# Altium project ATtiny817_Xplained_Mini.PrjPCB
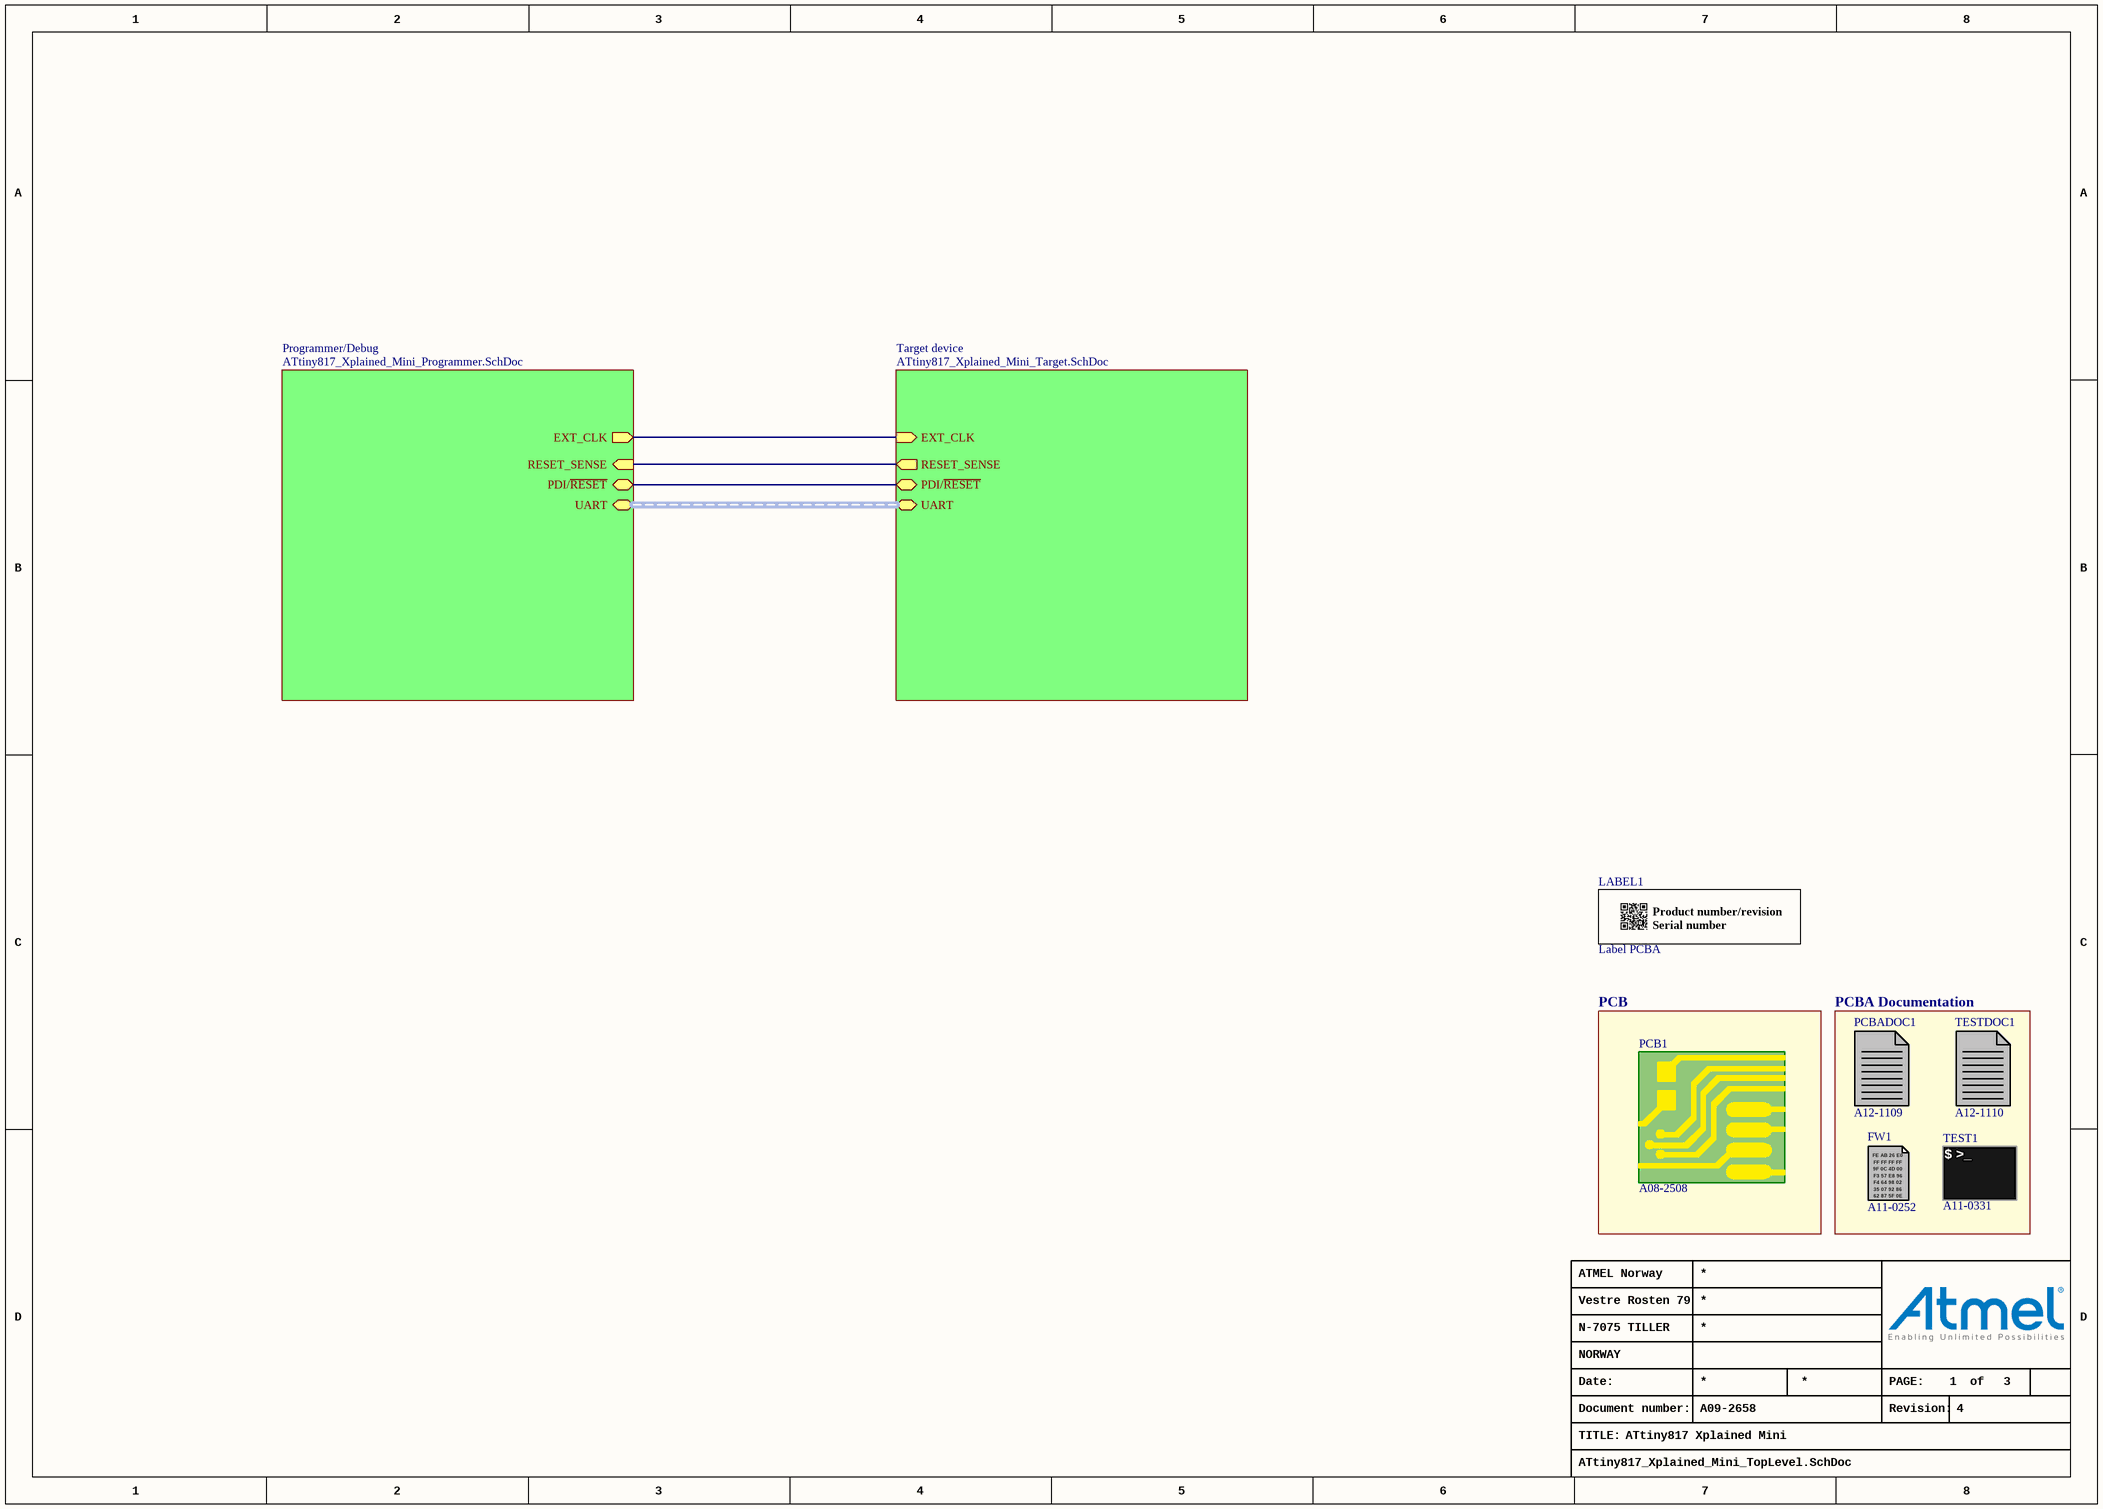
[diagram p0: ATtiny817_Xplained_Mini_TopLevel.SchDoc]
3 sheets, 69 parts. Net scope: hierarchical (ports join the sheet entries above them; power ports are global).
Board file: ATtiny817_Xplained_Mini.PcbDoc
Sheets:
  ATtiny817_Xplained_Mini_TopLevel.SchDoc
    Programmer/Debug = ATtiny817_Xplained_Mini_Programmer.SchDoc
    Target device = ATtiny817_Xplained_Mini_Target.SchDoc

## Sheet ATtiny817_Xplained_Mini_TopLevel.SchDoc: ATtiny817 Xplained Mini
size A3; Organization: ATMEL Norway; Address1: Vestre Rosten 79; Address2: N-7075 TILLER; Address3: NORWAY; DocumentNumber: A09-2658; Revision: 4; SheetNumber: 1; SheetTotal: 3; PageSetup: Record=PageOptions¦CenterHorizontal=True¦CenterVertical=True¦PrintScale=1.01¦XCorrection=1.00¦YCorrection=1.00¦PrintKind=1¦BorderSize=5000000¦LeftOffset=0¦BottomOffset=0¦Orientation=2¦PaperLength=1000¦PaperWidth=1000¦Scale=100¦PaperSource=7¦PrintQuality=-4¦MediaType=1¦DitherType=10¦PaperKind=Letter¦PrintScaleMode=1

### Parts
FW1  AN: A11-0252  (mechanical)
LABEL1  value Label PCBA  [AP8-00317]
PCB1  AN: A08-2508  (mechanical)
PCBADOC1  AN: A12-1109  (mechanical)
TEST1  AN: A11-0331  (mechanical)
TESTDOC1  AN: A12-1110  (mechanical)

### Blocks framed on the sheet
PCB: PCB1
PCBA Documentation: FW1 PCBADOC1 TEST1 TESTDOC1

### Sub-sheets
Programmer/Debug = ATtiny817_Xplained_Mini_Programmer.SchDoc: EXT_CLK (out), UART (harness UART), RESET_SENSE (in), PDI/~{RESET} (bidir)
Target device = ATtiny817_Xplained_Mini_Target.SchDoc: EXT_CLK (in), UART (harness UART), RESET_SENSE (out), PDI/~{RESET} (bidir)

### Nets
CLK_OUT: sheet Programmer/Debug/EXT_CLK, sheet Target device/EXT_CLK
RESET_SENSE: sheet Programmer/Debug/RESET_SENSE, sheet Target device/RESET_SENSE
UPDI: sheet Programmer/Debug/PDI/~{RESET}, sheet Target device/PDI/~{RESET}

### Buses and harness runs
harness sheet Programmer/Debug/UART = sheet Target device/UART

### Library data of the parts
FW1 = A11-0252: MEDBG firmware; PartGroup: Software,Firmware,Tools
LABEL1 = A09-0611: PCBA identification label PP Top White Gloss; PartGroup: Mechanical devices,Packaging materials,Printed Labels; Manufacturer: ACT Logimark AS; MPN: 505462
PCB1 = A08-2508: ATtiny807 Xplained Mini PCB documentation; PartGroup: Mechanical devices,Printed circuit boards; Value: ATtiny817 Xplained Mini PCB documentation
PCBADOC1 = A12-1109: ATtiny807 Xplained Mini PCBA documentation; PartGroup: Documentation,PCBA Documents,Atmel; Value: A09-2658 PCBA Files
TEST1 = A11-0331: Fixture test for ATtiny807 Xplained Pro; PartGroup: Software,Test software,Starter Kit; Value: ATtiny817 Xplained Mini test
TESTDOC1 = A12-1110: ATtiny807 Xplained Mini Test Instructions; PartGroup: Documentation,Procedures,Test Instructions; Value: ATtiny817 Xplained Mini Test Instructions

## Sheet ATtiny817_Xplained_Mini_Programmer.SchDoc: ATtiny817 Xplained Mini
size A3; Organization: ATMEL Norway; Address1: Vestre Rosten 79; Address2: N-7075 TILLER; Address3: NORWAY; DocumentNumber: A09-2658; Revision: 4; SheetNumber: 3; SheetTotal: 3; PageSetup: Record=PageOptions¦CenterHorizontal=True¦CenterVertical=True¦PrintScale=1.01¦XCorrection=1.00¦YCorrection=1.00¦PrintKind=1¦BorderSize=5000000¦LeftOffset=0¦BottomOffset=0¦Orientation=2¦PaperLength=1000¦PaperWidth=1000¦Scale=100¦PaperSource=7¦PrintQuality=-4¦MediaType=1¦DitherType=10¦PaperKind=A3 (297 x 420 mm)¦PrintScaleMode=1
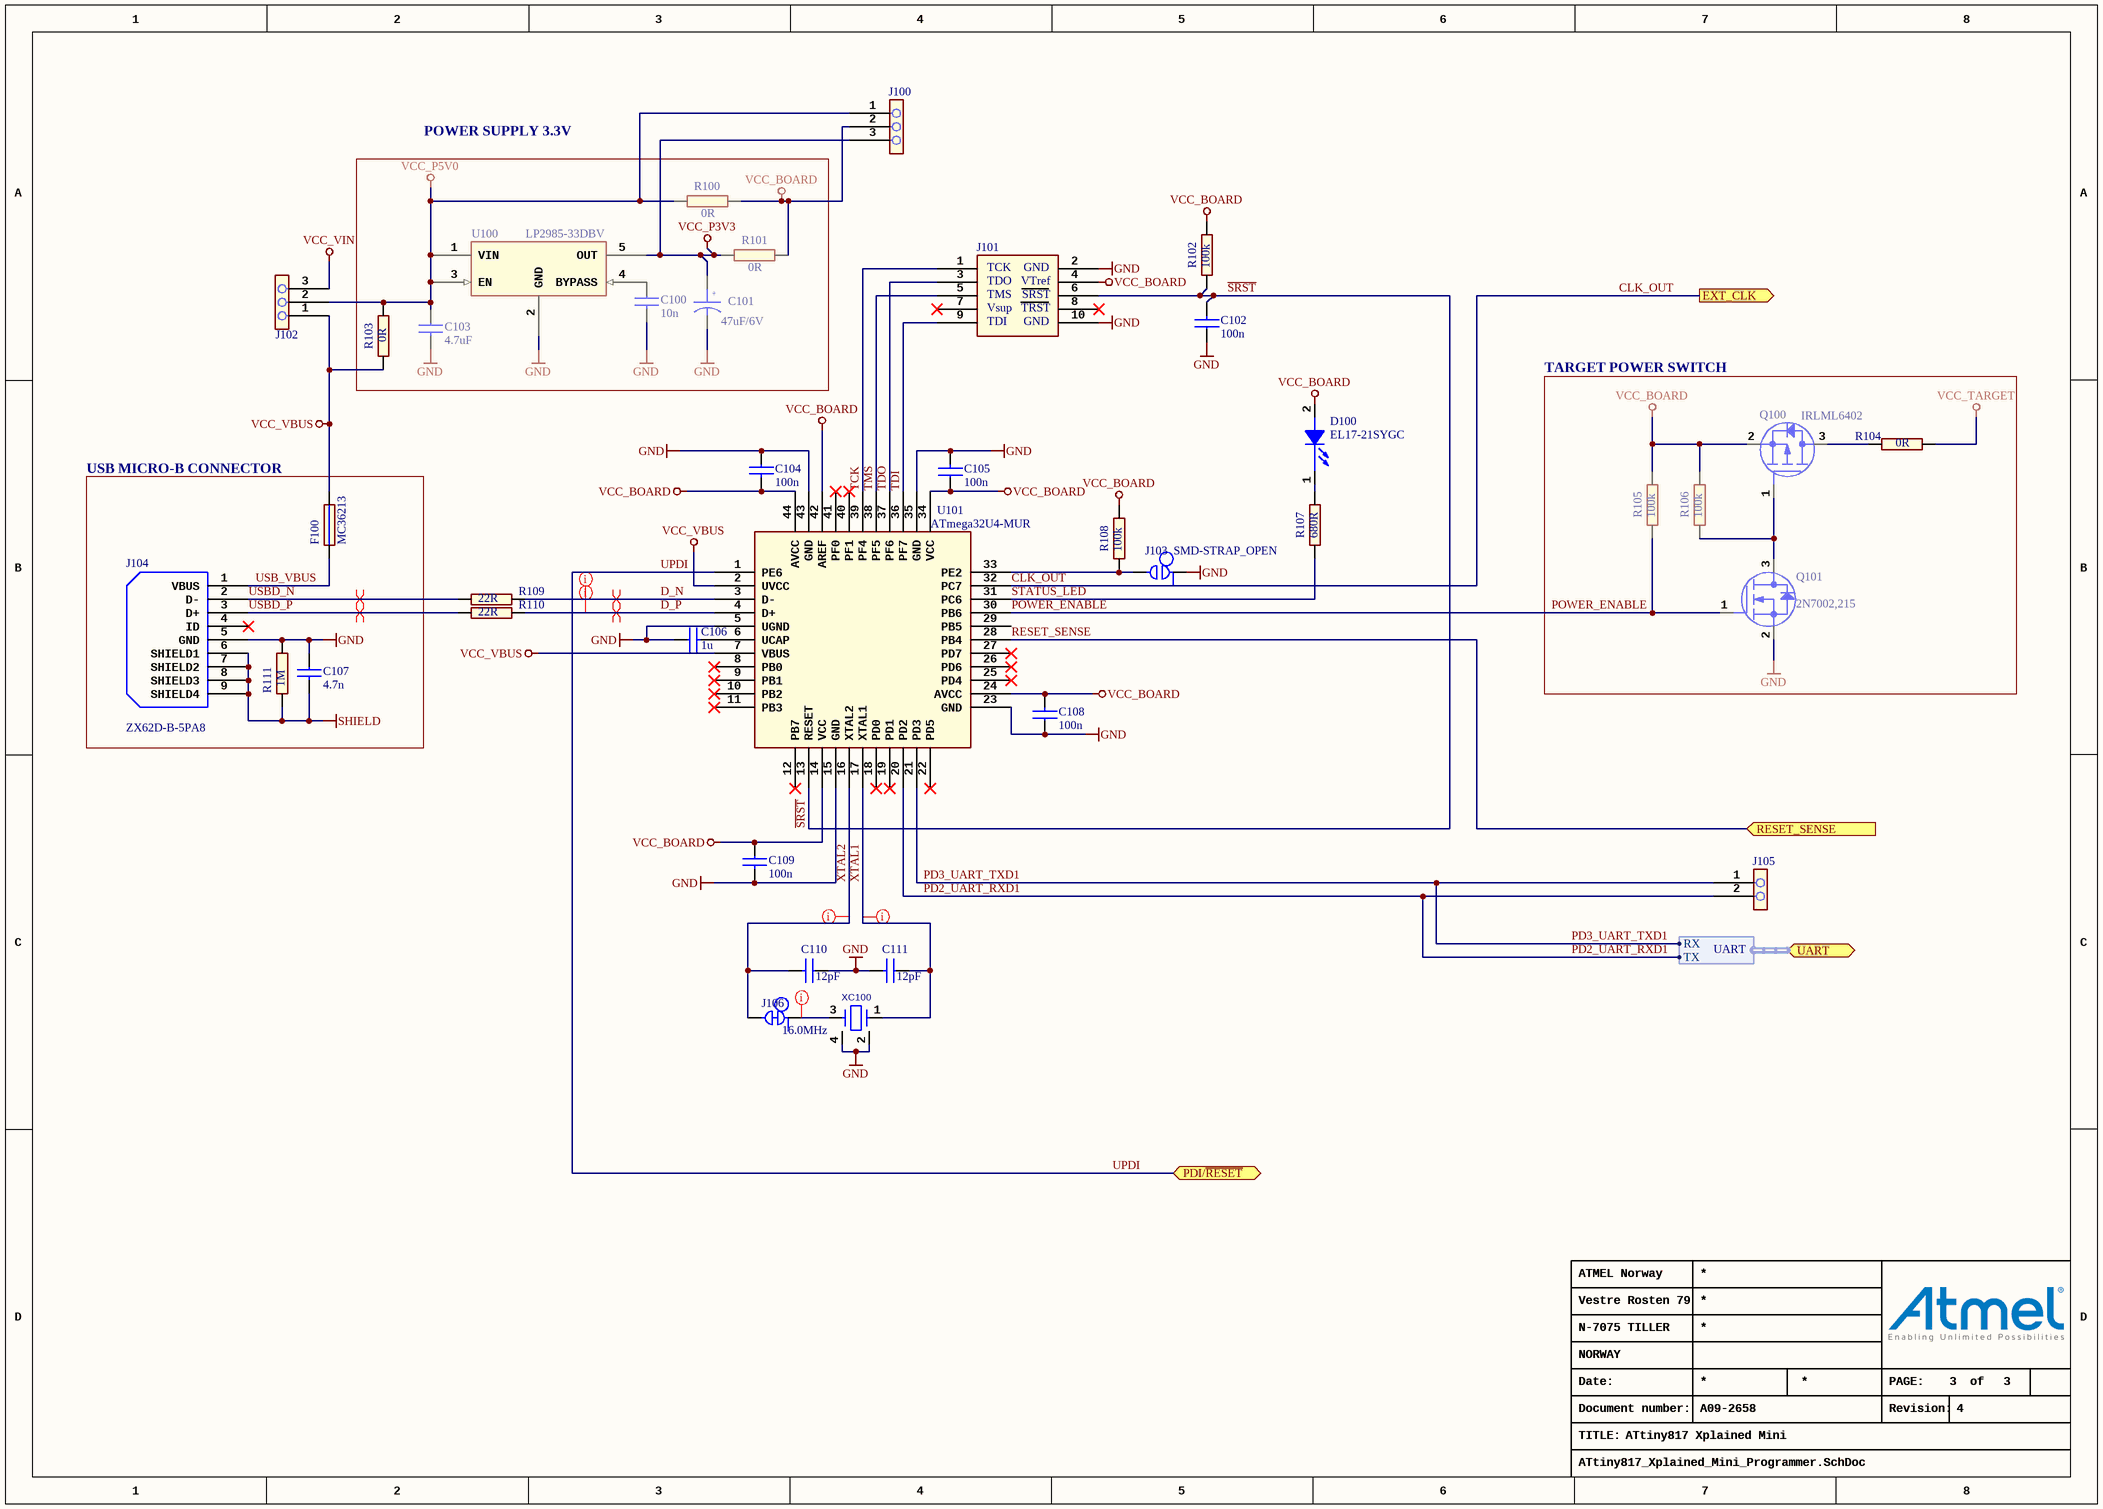
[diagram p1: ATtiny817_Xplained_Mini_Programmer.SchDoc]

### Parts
C100  value 10n  [AP1-00001]
C101  value 47uF/6V  [AP1-00008]
C102  value 100n  [AP1-00001]
C103  value 4.7uF  [AP1-00002]  (hidden comment: Farnell no.: 1833806)
C104  value 100n  [AP1-00001]
C105  value 100n  [AP1-00001]
C106  value 1u  [AP1-00001]
C107  value 4.7n  [AP1-00001]
C108  value 100n  [AP1-00001]
C109  value 100n  [AP1-00001]
C110  value 12pF  [AP1-00038]
C111  value 12pF  [AP1-00038]
D100  value EL17-21SYGC  [AP4-00013]
F100  value MC36213  [AP2-00002]  (hidden comment: Farnell no: 1861197)
J100  (no value)  [AP8-00745]
J101  (no value)  [AP8-00257]
J102  (no value)  [AP8-00745]
J103  value SMD-STRAP_OPEN  [AP9-00034]  (no BOM)
J104  value ZX62D-B-5PA8  [AP8-00851]  (hidden comment: 2,000 pieces per reel)
J105  (no value)  [AP8-00733]
J106  (no value)  [AP9-00044]  (net tie, no BOM)
Q100  value IRLML6402  [AP5-00002]
Q101  value 2N7002,215  [AP5-00002]
R100  value 0R  [AP2-00000]
R101  value 0R  [AP2-00000]
R102  value 100k  [AP2-00000]
R103  value 0R  [AP2-00000]
R104  value 0R  [AP2-00000]
R105  value 100k  [AP2-00000]
R106  value 100k  [AP2-00000]
R107  value 680R  [AP2-00000]
R108  value 100k  [AP2-00000]
R109  value 22R  [AP2-00000]
R110  value 22R  [AP2-00000]
R111  value 1M  [AP2-00000]
U100  value LP2985-33DBV  [AP6-00087]
U101  value ATmega32U4-MUR  [AP6-00375]
XC100  value 16.0MHz  [AP7-00061]

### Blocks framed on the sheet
POWER SUPPLY 3.3V: C100 C101 C103 R100 R101 R103 U100
TARGET POWER SWITCH: Q100 Q101 R104-R106
USB MICRO-B CONNECTOR: C107 F100 J104 R111

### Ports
EXT_CLK (out), PDI/~{RESET}, RESET_SENSE (in), UART (harness UART)

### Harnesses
UART: RX, TX

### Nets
GND: C100.2 C101.2 C102.1 C103.2 C104.1 C105.2 C106.1 C107.1 C108.1 C109.2 C110.1 C111.2 J101.2 J101.10 J103.1 J104.5(GND) Q101.2(S) R111.2 U100.2(GND) U101.5(UGND) U101.15(GND) U101.23(GND) U101.35(GND) U101.43(GND) U101.45(GND) XC100.2(GND) XC100.4(GND)
SHIELD: C107.2 J104.6(SHIELD1) J104.7(SHIELD2) J104.8(SHIELD3) J104.9(SHIELD4) R111.1
VCC_BOARD: C104.2 C105.1 C108.2 C109.1 D100.2(ANODE) J100.2 J101.4 Q100.2(S) R100.1 R101.2 R102.2 R105.2 R106.2 R108.2 U101.14(VCC) U101.24(AVCC) U101.34(VCC) U101.42(AREF) U101.44(AVCC)
VCC_P3V3: C101.1 J100.3 R101.1 U100.5(OUT)
VCC_P5V0: C103.1 J100.1 J102.2 R100.2 R103.2 U100.1(VIN) U100.3(EN)
VCC_TARGET: R104.2
VCC_VBUS: F100.2 J102.1 R103.1 U101.2(UVCC) U101.7(VBUS)
VCC_VIN: J102.3
CLK_OUT: U101.32(PC7) ; port EXT_CLK
D_N: R109.2 U101.3(D-)
D_P: R110.2 U101.4(D+)
PD2_UART_RXD1: J105.2 U101.20(PD2) ; port UART.TX
PD3_UART_TXD1: J105.1 U101.21(PD3) ; port UART.RX
POWER_ENABLE: Q101.1(G) R105.1 U101.30(PB6)
RESET_SENSE: U101.28(PB4) ; port RESET_SENSE
~{SRST}: C102.2 J101.6 R102.1 U101.13(RESET)
STATUS_LED: R107.2 U101.31(PC6)
TCK: J101.1 U101.39(PF4)
TDI: J101.9 U101.36(PF7)
TDO: J101.3 U101.37(PF6)
TMS: J101.5 U101.38(PF5)
UPDI: U101.1(PE6) ; port PDI/~{RESET}
USB_VBUS: F100.1 J104.1(VBUS)
USBD_N: J104.2(D-) R109.1
USBD_P: J104.3(D+) R110.1
XTAL1: C111.1 U101.17(XTAL1) XC100.1(IN)
XTAL2: C110.2 J106.2 U101.16(XTAL2)
NetC100_1: C100.1 U100.4(BYPASS)
NetC106_2: C106.2 U101.6(UCAP)
NetD100_1: D100.1(CATHODE) R107.1
NetJ103_2: J103.2 R108.1 U101.33(PE2)
NetJ106_1: J106.1 XC100.3(OUT)
NetQ100_1: Q100.1(G) Q101.3(D) R106.1
NetQ100_3: Q100.3(D) R104.1

Not connected (* = marked no-connect by the designer): J101 7* 8*; J104 4(ID)*; U101 8(PB0)* 9(PB1)* 10(PB2)* 11(PB3)* 12(PB7)* 18(PD0)* 19(PD1)* 22(PD5)* 25(PD4)* 26(PD6)* 27(PD7)* 29(PB5) 40(PF1)* 41(PF0)*

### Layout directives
differential pair: D_N, D_P, USBD_N, USBD_P
rule Assembly Testpoint Usage [Testpoint - Not Allowed    Multiple - Not Allowed]: D_N, D_P, NetJ106_1, XTAL1, XTAL2

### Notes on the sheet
- Date:
- PAGE:
- of
- TITLE:
- Document number:
- Revision:

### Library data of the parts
C100 = A01-0050: Ceramic capacitor, SMD 0402, X7R, 25V, +/-10%; PartGroup: Capacitors,Ceramic,SMD 0402; Manufacturer: YAGEO CORP; MPN: CC0402KRX7R8BB103; TemperatureRange: -55 - +125 deg C
C101 = A01-0292: SMD tantalum capacitor, precision molded chip, ESR=0,5; PartGroup: Capacitors,Tantalum; Manufacturer: Kemet; MPN: T494B476M006AT; TemperatureRange: -55 to +85 deg.C
C102 C104 C105 C108 C109 = A01-0246: Ceramic capacitor, SMD 0402, X7R, 16V, +/-10%; PartGroup: Capacitors,Ceramic,SMD 0402; Manufacturer: Kemet; MPN: C0402C104K4RACTU; TemperatureRange: -55 - +125 deg C
C103 = A01-0502: Ceramic capacitor, SMD 0603, X5R, 10V, ±10 %; PartGroup: Capacitors,Ceramic,SMD 0603; Manufacturer: AVX; MPN: 0603ZD475KAT2A; Tolerance: Â±10%; TemperatureRange: Ã‚â€“55 to +85 deg C
C106 = A01-0286: Ceramic capacitor, SMD 0402, X5R, 6.3V, +/-10% (de26942); PartGroup: Capacitors,Ceramic,SMD 0402; Manufacturer: Kemet; MPN: C0402C105K9PAC; TemperatureRange: -55 to 85 deg C
C107 = A01-0046: Ceramic capacitor, SMD 0402, X7R, 25V, +/-10% (de35287); PartGroup: Capacitors,Ceramic,SMD 0402; Manufacturer: PHYCOMP; MPN: 2238 587 15632; TemperatureRange: -55 - +125 deg C
C110 C111 = A01-0355: Ceramic capacitor, SMD 0402, NP0, 50V, +/-5% (de19819); PartGroup: Capacitors,Ceramic,SMD 0402; Manufacturer: Kyocera-elco; MPN: CM05CG120J50AH; Tolerance: 5%; TemperatureRange: -55 - +125 deg C
D100 = A10-0018: LED, Green, Wave length=575nm, SMD 0805, ±70°; PartGroup: Opto,LEDs,SMD; Manufacturer: Everlight; TemperatureRange: -40 - +85 deg C
F100 = A02-0622: Resetable PTC fuse, Ih = 0.5A, It = 1.0A, 0805 package; PartGroup: Resistors,Resettable fuses,SMD; Manufacturer: Multicomp; TemperatureRange: -40°C to + 85°C
J100 J102 = A08-1799: 1x3 pin header, 2.54mm pitch, Pin-in-Paste THM, 1mm hole; PartGroup: Mechanical devices,Connectors,Pin headers; Manufacturer: SAMTEC; Value: HMTSW-103-23-F-S-237
J101 = A08-0385: 2x5 pin header, 1.27mm pitch, THM; PartGroup: Mechanical devices,Connectors,Pin headers; Manufacturer: Garry; MPN: 176-2-010-0-T-XS0-0730; Value: PIN HEADER 2x5
J103 = A09-0483: Default open SMD strap; PartGroup: Mechanical devices,PCB implemented components
J104 = A08-2092: Micro USB B Connector, Standard SMT + DIP; PartGroup: Mechanical devices,Connectors,USB; Manufacturer: HIROSE; MPN: ZX62D-B-5PA8(30)
J105 = A08-1754: 1x2 pin header, 2.54mm pitch, Pin-in-Paste THM; PartGroup: Mechanical devices,Connectors,Pin headers; Manufacturer: SAMTEC; Value: HMTSW-102-23-F-S-237; TemperatureRange: - 55 deg C to + 125 deg C
J106 = A09-0783: Default closed SMD strap, 0603 size; PartGroup: Mechanical devices,PCB implemented components; Value: SMD-STRAP_0603_CLOSED
Q100 = A05-0087: P-ch. MOSFET. -30V, -3.7A continuous,RDS(ON)=0.05Ohm@VGS=-4,5V, RDS(ON)=0.08Ohm@VGS=-2.5V; PartGroup: Transistors,Power FET,SMD; Manufacturer: International Rectifier; MPN: IRLML6402PBF; TemperatureRange: -55 - +150 deg C
Q101 = A05-0085: N-Channel MOSFET. 60V, 0.300A continuous, 1.2A Peak. RDS(ON) = 3.8Ohm@VGS=4.5V, VGS(th)<2.5V; PartGroup: Transistors,Small signal FET,SMD; Manufacturer: NXP; TemperatureRange: -65 to 150 deg C
R100 R101 R103 R104 = A02-0163: RES 0.0 OHM 1/16W 0402 SMD; PartGroup: Resistors,SMD,0402 1%; Manufacturer: (n/a); MPN: RMCF0402ZT0R00; Tolerance: 1 %; TemperatureRange: -55 - +125 deg C
R102 R105 R106 R108 = A02-0260: Thick film resistor, SMD 0402, 1/16W, 1%; PartGroup: Resistors,SMD,0402 1%; Manufacturer: ASJ; MPN: CR10-1003-FK; TemperatureRange: -55ï¿½ to +125ï¿½C
R107 = A02-0208: Thick film resistor, SMD 0402, 1/16W, 1%; PartGroup: Resistors,SMD,0402 1%; Manufacturer: ASJ; MPN: CR10-6800-FK; TemperatureRange: -55 - +125 deg C
R109 R110 = A02-0172: Thick film resistor, SMD 0402, 1/16W, 1% (de23607); PartGroup: Resistors,SMD,0402 1%; Manufacturer: Samsung; MPN: RC100SF22R0CS; TemperatureRange: -55 - +125 deg C
R111 = A02-0284: Thick film resistor, SMD 0402, 1/16W, 1%; PartGroup: Resistors,SMD,0402 1%; Manufacturer: ASJ; MPN: CR10-1004-FK; TemperatureRange: -55 - +125 deg C
U100 = A06-1099: LDO 3.3V 150mA SOT23-5 1.5% (cer. cap); PartGroup: Integrated Circuits,Regulators,Linear; Manufacturer: Texas Instruments; TemperatureRange: -40 - +125 deg. C
U101 = A06-0305: ATmega32U4 QFN package; PartGroup: Integrated Circuits,MCU, MPU, DSP,AVR MCU; Manufacturer: ATMEL
XC100 = A07-0078: 16MHz uXtal, 3.2 x 2.5 mm SMD, CL=9pF, 15PPM, ESR=80ohm(Max.; PartGroup: Frequency devices,Crystals,SMD; Manufacturer: Epson Toyocom; MPN: TSX-3225 16.0000MF09Z-AC3; TemperatureRange: -40Â°C to +85Â°C

## Sheet ATtiny817_Xplained_Mini_Target.SchDoc: ATtiny817 Xplained Mini
size A3; Organization: ATMEL Norway; Address1: Vestre Rosten 79; Address2: N-7075 TILLER; Address3: NORWAY; DocumentNumber: A09-2658; Revision: 4; SheetNumber: 2; SheetTotal: 3; PageSetup: Record=PageOptions¦CenterHorizontal=True¦CenterVertical=True¦PrintScale=1.01¦XCorrection=1.00¦YCorrection=1.00¦PrintKind=1¦BorderSize=5000000¦LeftOffset=0¦BottomOffset=0¦Orientation=2¦PaperLength=1000¦PaperWidth=1000¦Scale=100¦PaperSource=7¦PrintQuality=-4¦MediaType=1¦DitherType=10¦PaperKind=A3 (297 x 420 mm)¦PrintScaleMode=1
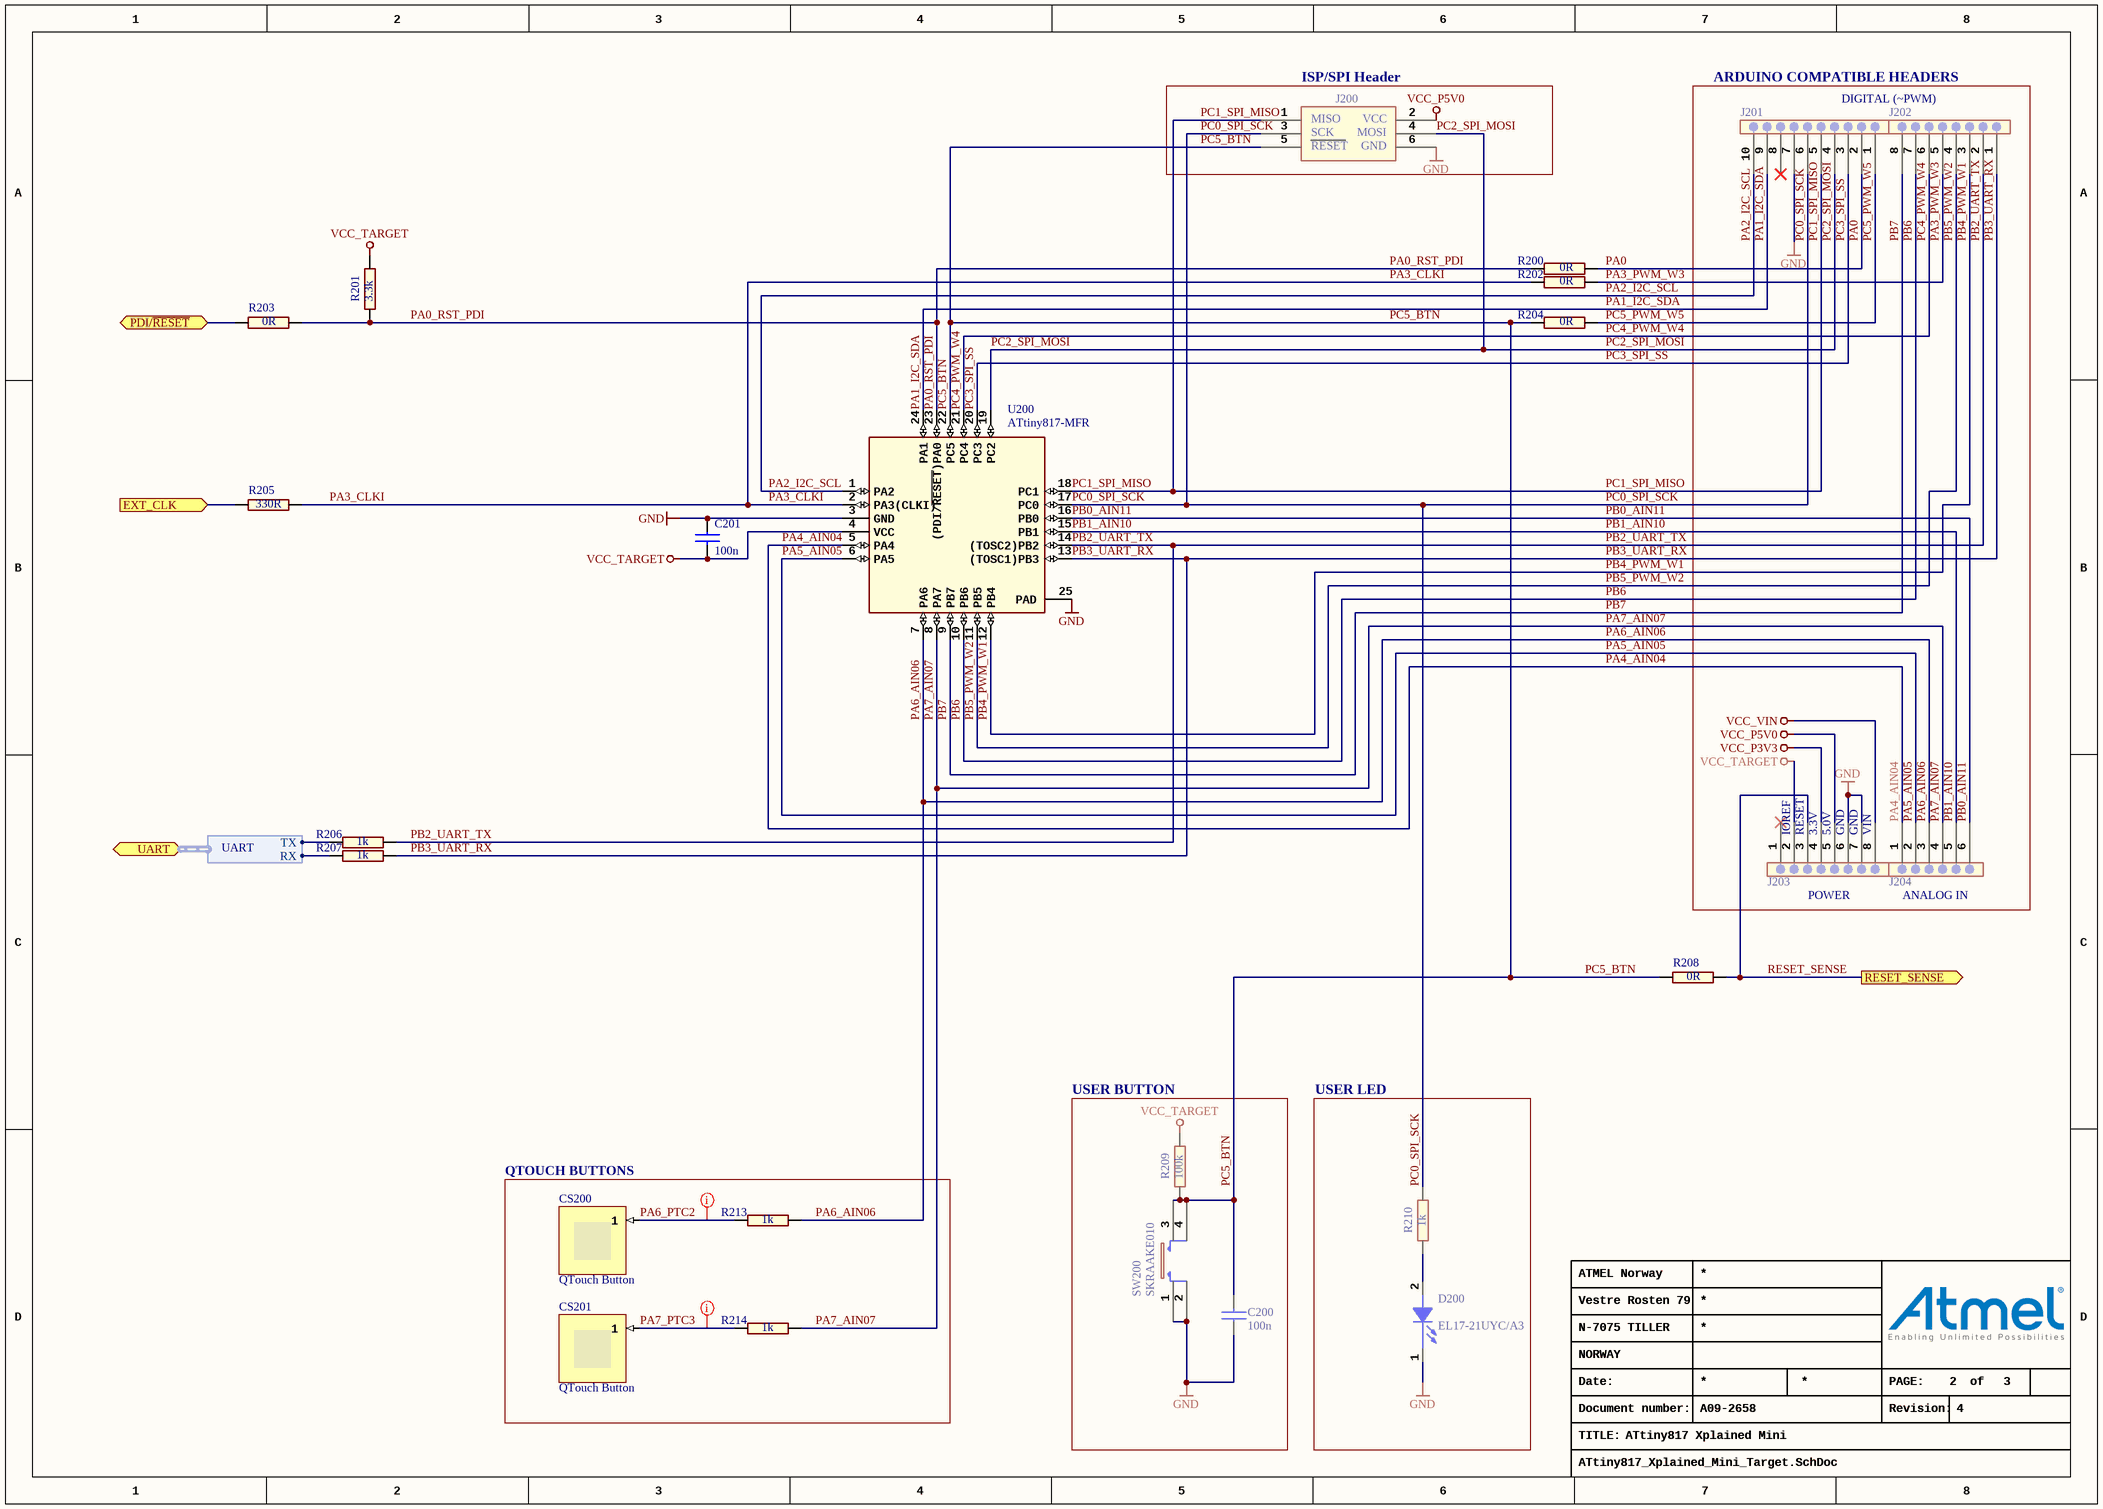
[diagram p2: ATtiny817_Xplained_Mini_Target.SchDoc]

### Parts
C200  value 100n  [AP1-00001]
C201  value 100n  [AP1-00001]
CS200  QTouch Button  (no BOM)
CS201  QTouch Button  (no BOM)
D200  value EL17-21UYC/A3  [AP4-00013]
J200  (no value)  [AP8-00182]
J201  (no value)  [AP8-00822]
J202  (no value)  [AP8-00823]
J203  (no value)  [AP8-00823]
J204  (no value)  [AP8-00824]
R200  value 0R  [AP2-00000]
R201  value 3.3k  [AP2-00000]
R202  value 0R  [AP2-00000]
R203  value 0R  [AP2-00000]
R204  value 0R  [AP2-00000]
R205  value 330R  [AP2-00000]
R206  value 1k  [AP2-00000]
R207  value 1k  [AP2-00000]
R208  value 0R  [AP2-00000]
R209  value 100k  [AP2-00000]
R210  value 1k  [AP2-00000]
R213  value 1k  [AP2-00011]
R214  value 1k  [AP2-00011]
SW200  value SKRAAKE010  [AP8-00137]
U200  value ATtiny817-MFR  [AP6-00459]  (hidden comment: ATtiny807)

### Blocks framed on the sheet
ISP/SPI Header: J200
ARDUINO COMPATIBLE HEADERS: J201-J204
USER BUTTON: C200 R209 SW200
USER LED: D200 R210
QTOUCH BUTTONS: CS200 CS201 R213 R214

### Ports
EXT_CLK (in), PDI/~{RESET} (bidir), RESET_SENSE (out), UART (harness UART)

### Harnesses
UART: RX, TX

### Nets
GND: C200.1 C201.1 D200.1(CATHODE) J200.6 J201.7 J203.6 J203.7 SW200.1 SW200.2 U200.3(GND) U200.25(PAD)
VCC_P3V3: J203.4
VCC_P5V0: J200.2 J203.5
VCC_TARGET: C201.2 J203.2 R201.2 R209.2 U200.4(VCC)
VCC_VIN: J203.8
CLK_OUT: R205.2 ; port EXT_CLK
PA0: J201.2 R200.2
PA0_RST_PDI: R200.1 R201.1 R203.2 U200.23((PDI/~{RESET})PA0)
PA1_I2C_SDA: J201.9 U200.24(PA1)
PA2_I2C_SCL: J201.10 U200.1(PA2)
PA3_CLKI: R202.1 R205.1 U200.2(PA3(CLKI))
PA3_PWM_W3: J202.5 R202.2
PA4_AIN04: J204.1 U200.5(PA4)
PA5_AIN05: J204.2 U200.6(PA5)
PA6_AIN06: J204.3 R213.2 U200.7(PA6)
PA6_PTC2: CS200.1 R213.1
PA7_AIN07: J204.4 R214.2 U200.8(PA7)
PA7_PTC3: CS201.1 R214.1
PB0_AIN11: J204.6 U200.16(PB0)
PB1_AIN10: J204.5 U200.15(PB1)
PB2_UART_TX: J202.2 R206.2 U200.14((TOSC2)PB2)
PB3_UART_RX: J202.1 R207.2 U200.13((TOSC1)PB3)
PB4_PWM_W1: J202.3 U200.12(PB4)
PB5_PWM_W2: J202.4 U200.11(PB5)
PB6: J202.7 U200.10(PB6)
PB7: J202.8 U200.9(PB7)
PC0_SPI_SCK: J200.3 J201.6 R210.2 U200.17(PC0)
PC1_SPI_MISO: J200.1 J201.5 U200.18(PC1)
PC2_SPI_MOSI: J200.4 J201.4 U200.19(PC2)
PC3_SPI_SS: J201.3 U200.20(PC3)
PC4_PWM_W4: J202.6 U200.21(PC4)
PC5_BTN: C200.2 J200.5 R204.1 R208.1 R209.1 SW200.3 SW200.4 U200.22(PC5)
PC5_PWM_W5: J201.1 R204.2
PD2_UART_RXD1: R206.1 ; port UART.TX
PD3_UART_TXD1: R207.1 ; port UART.RX
RESET_SENSE: J203.3 R208.2 ; port RESET_SENSE
UPDI: R203.1 ; port PDI/~{RESET}
NetD200_2: D200.2(ANODE) R210.1

Not connected (* = marked no-connect by the designer): J201 8*; J203 1*

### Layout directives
rule Assembly Testpoint Usage [Testpoint - Not Allowed    Multiple - Not Allowed]: PA6_PTC2, PA7_PTC3

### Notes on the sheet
- DIGITAL (~PWM)
- (near J203) IOREF
- (near J203) RESET
- (near J203) 3.3V
- (near J203) 5.0V
- (near J203) GND
- VIN
- (near J203) POWER
- ANALOG IN
- Date:
- PAGE:
- of
- TITLE:
- Document number:
- Revision:

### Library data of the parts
C200 C201 = A01-0246: as C102 on sheet ATtiny817_Xplained_Mini_Programmer
CS200 CS201 = QTouchButton: ConfiguratorName: ATMEL_TOUCH; ConfigurationParameters: {}__sensorid[1]{}width[8]{}height[8]{}
D200 = A10-0019: LED, Yellow, Wave length=591nm, SMD 0805, ±70°; PartGroup: Opto,LEDs,SMD; Manufacturer: Everlight; MPN: 17-21UYC/S530-A3/TR8; TemperatureRange: -40 to +85 deg C
J200 = A08-0538: 2x3 pin header, 2.54 mm pitch, THM; PartGroup: Mechanical devices,Connectors,Pin headers; Manufacturer: SAMTEC; Value: MTSW-103-08-L-D-276; TemperatureRange: max. 125 degrees
J201 = A08-2026: 1x10 receptacle pin header, low insertion force, 2.54mm pitch THM, Pin in Paste; PartGroup: Mechanical devices,Connectors,Pin header receptacle; Manufacturer: SAMTEC; Value: SSQ-110-21-F-S
J202 J203 = A08-2025: 1x8 receptacle pin header, low insertion force, 2.54mm pitch THM, Pin in Paste; PartGroup: Mechanical devices,Connectors,Pin header receptacle; Manufacturer: SAMTEC; Value: SSQ-108-21-F-S
J204 = A08-2024: 1x6 receptacle pin header, low insertion force, 2.54mm pitch THM; PartGroup: Mechanical devices,Connectors,Pin header receptacle; Manufacturer: SAMTEC; Value: SSQ-106-21-F-S
R200 R202-R204 R208 = A02-0163: as R100 on sheet ATtiny817_Xplained_Mini_Programmer
R201 = A02-0224: Thick film resistor, SMD 0402, 1/16W, 1%; PartGroup: Resistors,SMD,0402 1%; Manufacturer: ASJ; MPN: CR10-3301-FK; TemperatureRange: -55 - +125 deg C
R205 = A02-0200: Thick film resistor, SMD 0402, 1/16W, 1%; PartGroup: Resistors,SMD,0402 1%; Manufacturer: ASJ; MPN: CR10-3300-FK; TemperatureRange: -55 - +125 deg C
R206 R207 R210 R213 R214 = A02-0212: Thick film resistor, SMD 0402, 1/16W, 1%; PartGroup: Resistors,SMD,0402 1%; Manufacturer: ASJ; MPN: CR10-1001-FK; TemperatureRange: -55 - +125 deg C
R209 = A02-0260: as R102 on sheet ATtiny817_Xplained_Mini_Programmer
SW200 = A08-0790: 6.2x6.2 mm SMD tact switch, same as A08-0091 but less force is needed; PartGroup: Mechanical devices,Switches,SMD; Manufacturer: ALPS; TemperatureRange: -30 - +90 deg C
U200 = A06-1373: Atmel 8-bit RISC MCU; PartGroup: Integrated Circuits,MCU, MPU, DSP,AVR MCU; TemperatureRange: -40Â°C +125Â°C; ComponentStatus: 'Active (verified)'

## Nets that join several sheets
GND: ATtiny817_Xplained_Mini_Programmer (27 pins), ATtiny817_Xplained_Mini_Target (11 pins)
VCC_P3V3: ATtiny817_Xplained_Mini_Programmer (C101.1 J100.3 R101.1 U100.5), ATtiny817_Xplained_Mini_Target (J203.4)
VCC_P5V0: ATtiny817_Xplained_Mini_Programmer (7 pins), ATtiny817_Xplained_Mini_Target (J200.2 J203.5)
VCC_TARGET: ATtiny817_Xplained_Mini_Programmer (R104.2), ATtiny817_Xplained_Mini_Target (5 pins)
VCC_VIN: ATtiny817_Xplained_Mini_Programmer (J102.3), ATtiny817_Xplained_Mini_Target (J203.8)
CLK_OUT: ATtiny817_Xplained_Mini_Programmer (U101.32), ATtiny817_Xplained_Mini_Target (R205.2)
PD2_UART_RXD1: ATtiny817_Xplained_Mini_Programmer (J105.2 U101.20), ATtiny817_Xplained_Mini_Target (R206.1)
PD3_UART_TXD1: ATtiny817_Xplained_Mini_Programmer (J105.1 U101.21), ATtiny817_Xplained_Mini_Target (R207.1)
RESET_SENSE: ATtiny817_Xplained_Mini_Programmer (U101.28), ATtiny817_Xplained_Mini_Target (J203.3 R208.2)
UPDI: ATtiny817_Xplained_Mini_Programmer (U101.1), ATtiny817_Xplained_Mini_Target (R203.1)

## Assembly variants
Default_assembly: not fitted C107 J100 J101 J102 J105 J200 J201 J202 J203 J204 R101 R111 R200 R201 R204 R205 R208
